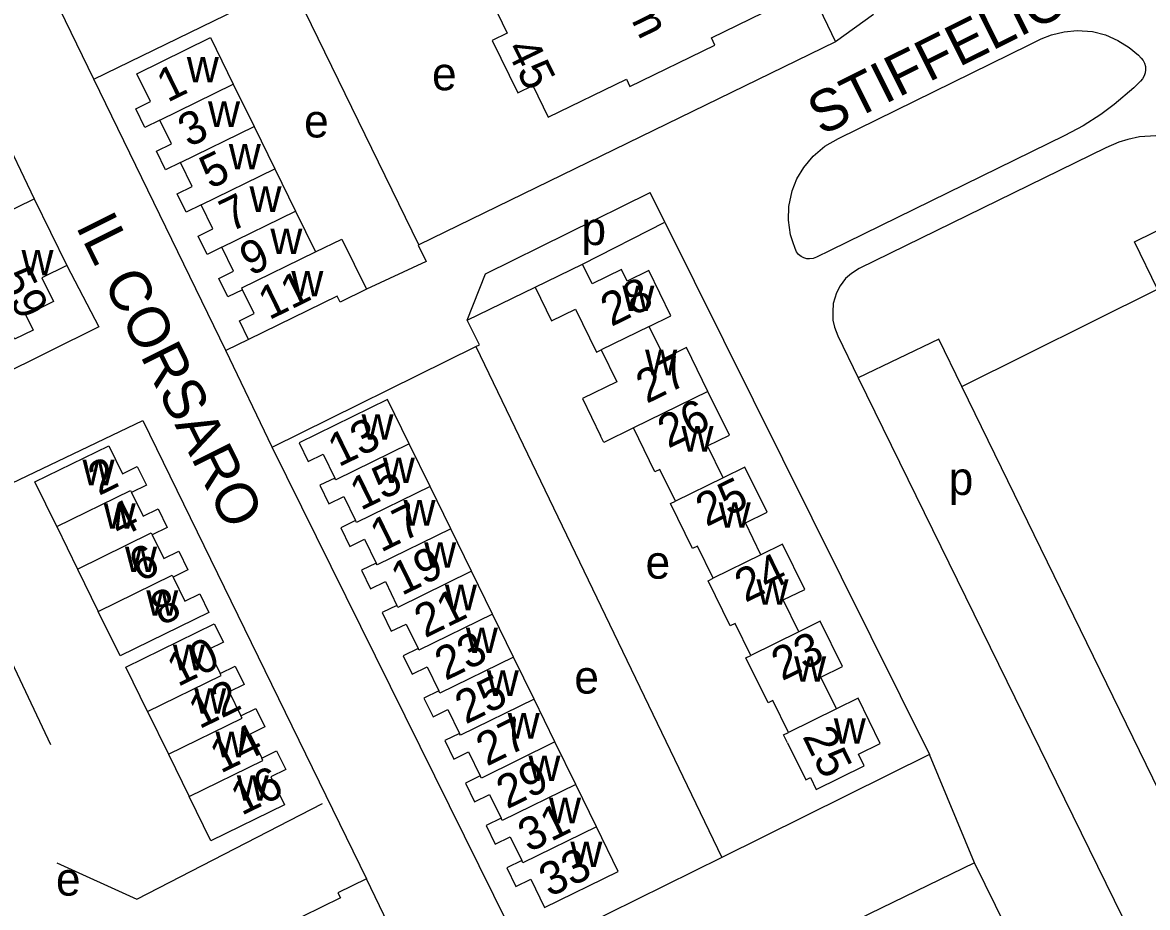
# Model space of a CAD drawing. Extents: x 159441 to 162086, y 388175 to 389787.
# Drawn here: x 161032.2 to 161168.1, y 389007.5 to 389114.4 of the extents above; entities that cross this region are included whole.
import ezdxf

# ---------------------------------------------------------------- set-up
doc = ezdxf.new("R2010")
doc.units = 0
for name, color, linetype in [('BLT_Basislijn', 7, 'Continuous'), ('BLT_Bebouwing', 7, 'Continuous'), ('BLT_Centroide', 7, 'Continuous'), ('BLT_Huisnummer', 7, 'Continuous'), ('BLT_Huisnummer_ tussenligend', 7, 'Continuous'), ('BLT_Huisnummer_reeks', 7, 'Continuous'), ('BLT_Onderverdeling_panden', 7, 'Continuous'), ('BLT_Straatnaam', 7, 'Continuous'), ('BLT_Vlakafsluiter', 7, 'Continuous')]:
    doc.layers.add(name, color=color, linetype=linetype)

msp = doc.modelspace()

# ---------------------------------------------------------------- linework, layer by layer
at = {"layer": 'BLT_Basislijn'}
for p, q in [((161040.84, 389107.5), (161034.48, 389120.57)), ((161040.84, 389107.5), (161064.68, 389119.13)), ((161080.09, 389087.51), (161064.68, 389119.13)), ((161134.99, 389115.31), (161130.39, 389112.02)), ((161056.77, 389074.76), (161040.84, 389107.5)), ((161088.14, 389084.03), (161108, 389093.82)), ((161109.79, 389090.25), (161108, 389093.82)), ((161080.95, 389085.51), (161073.75, 389082.15)), ((161085.9, 389078.44), (161088.14, 389084.03)), ((161145.68, 389070.41), (161169.3, 389082.16)), ((161059.51, 389076.1), (161056.77, 389074.76)), ((161062.38, 389063.07), (161056.77, 389074.76)), ((161086.97, 389075.23), (161116.67, 389013.57)), ((161022.8, 389054.2), (161035.58, 389027.21))]:
    msp.add_line(p, q, dxfattribs=at)
for points in [[(161115.18, 389143.74), (161130.39, 389112.02)], [(161130.39, 389112.02), (161080.09, 389087.51)], [(161029.44, 389101.75), (161033.6, 389093.07)], [(161176.24, 389092.68), (161172.92, 389099.4), (161172.69, 389099.74), (161172.4, 389100.01), (161171.67, 389100.34), (161171.1, 389100.47), (161169.11, 389100.68), (161167.1, 389100.54), (161165.72, 389100.25), (161164.64, 389099.91), (161163.06, 389099.23), (161133.27, 389084.67), (161132.32, 389084.05), (161131.62, 389083.46), (161130.97, 389082.58), (161130.54, 389081.72), (161130.13, 389080.43), (161130.07, 389079.41), (161130.08, 389078.44), (161130.29, 389077.57), (161130.67, 389076.54), (161133.15, 389071.47)], [(161169.3, 389082.16), (161166.52, 389087.87), (161176.24, 389092.68)], [(161099.83, 389085.19), (161109.79, 389090.25)], [(161109.79, 389090.25), (161141.77, 389025.97)], [(161080.09, 389087.51), (161080, 389087.46), (161080.95, 389085.51)], [(161037.55, 389085.01), (161041.45, 389077.62), (160998.37, 389056.26), (160996.9, 389059.31)], [(161085.9, 389078.44), (161094.12, 389082.4)], [(161086.97, 389075.23), (161087.39, 389075.43), (161085.9, 389078.44)], [(161145.68, 389070.41), (161142.9, 389076.12), (161133.15, 389071.47)], [(161062.38, 389063.07), (161086.97, 389075.23)], [(161133.15, 389071.47), (161220.85, 388892.53), (161222.4, 388889.35)], [(161222.4, 388889.35), (161222.83, 388889.21), (161223.51, 388889.06), (161224.2, 388888.98), (161224.89, 388888.98), (161225.58, 388889.07), (161226.26, 388889.23), (161226.91, 388889.46), (161227.53, 388889.78), (161228.12, 388890.16), (161228.65, 388890.6), (161229.13, 388891.1), (161229.55, 388891.66), (161229.9, 388892.26), (161230.18, 388892.89), (161230.39, 388893.56), (161230.52, 388894.24), (161230.57, 388894.93), (161230.54, 388895.63), (161230.43, 388896.32), (161230.24, 388896.99), (161229.98, 388897.63), (161145.68, 389070.41)], [(161014.05, 389050.68), (161046.74, 389066.3), (161073.76, 389010.99)], [(161092.7, 389001.72), (161062.38, 389063.07)], [(161141.77, 389025.97), (161116.67, 389013.57)], [(161036.37, 389012.9), (161046.01, 389008.52), (161068.43, 389020.09)], [(161116.67, 389013.57), (161092.7, 389001.72)], [(161147.21, 389012.91), (161121.83, 389000.58)], [(161144.66, 388953.98), (161170.1, 388966.39), (161147.21, 389012.91)]]:
    msp.add_lwpolyline(points, dxfattribs=at)
msp.add_lwpolyline([(161130.78, 389100.36), (161153.79, 389111.67), (161155.24, 389112.38), (161156.5, 389112.88), (161158.03, 389113.23), (161159.61, 389113.4), (161161.44, 389113.26), (161163, 389112.88), (161164.51, 389112.19), (161165.87, 389111.34), (161167, 389110.4), (161167.31, 389110.06), (161167.55, 389109.77), (161167.71, 389109.43), (161167.83, 389109.03), (161167.85, 389108.64), (161167.8, 389108.28), (161167.69, 389107.9), (161167.48, 389107.57), (161167.23, 389107.26), (161166.44, 389106.47), (161164.06, 389104.44), (161162.44, 389103.24), (161160.32, 389101.89), (161158.1, 389100.7), (161129.76, 389086.84), (161128.11, 389086.02), (161127.71, 389085.86), (161127.28, 389085.81), (161126.92, 389085.84), (161126.58, 389085.95), (161126.26, 389086.12), (161125.94, 389086.36), (161125.71, 389086.68), (161125.52, 389087.06), (161125.24, 389087.86), (161124.98, 389088.71), (161124.72, 389090.51), (161124.76, 389092.14), (161125.16, 389094.02), (161125.75, 389095.47), (161126.57, 389096.84), (161127.69, 389098.22), (161129.1, 389099.42)], close=True, dxfattribs=at)
at = {"layer": 'BLT_Bebouwing'}
for p, q in [((161057.67, 389106.93), (161060.18, 389101.81)), ((161060.18, 389101.81), (161062.69, 389096.69)), ((161062.69, 389096.69), (161065.2, 389091.57)), ((161065.2, 389091.57), (161067.61, 389086.67)), ((161094.12, 389082.4), (161099.83, 389085.19)), ((161073.75, 389082.15), (161070.58, 389080.6)), ((161081.43, 389058.35), (161078.92, 389063.49)), ((161083.94, 389053.23), (161081.43, 389058.35)), ((161036.34, 389053.51), (161038.86, 389048.38)), ((161086.45, 389048.1), (161083.94, 389053.23)), ((161038.86, 389048.38), (161041.36, 389043.26)), ((161088.98, 389042.93), (161086.45, 389048.1)), ((161091.51, 389037.75), (161088.98, 389042.93)), ((161094, 389032.66), (161091.51, 389037.75)), ((161096.52, 389027.5), (161094, 389032.66)), ((161047.3, 389031.18), (161049.83, 389026.03)), ((161099.03, 389022.38), (161096.52, 389027.5)), ((161049.83, 389026.03), (161052.33, 389020.92)), ((161101.53, 389017.26), (161099.03, 389022.38)), ((161077.03, 389004.24), (161073.76, 389010.99))]:
    msp.add_line(p, q, dxfattribs=at)
for points in [[(161118.04, 389131.1), (161108.61, 389126.51), (161107.47, 389128.84), (161097.17, 389123.83), (161098.32, 389121.48), (161088.89, 389116.88), (161090.75, 389113.06), (161088.94, 389112.18), (161092.02, 389105.86), (161093.84, 389106.74), (161095.7, 389102.92), (161105.15, 389107.53)], [(161105.15, 389107.53), (161105.58, 389106.64), (161115.84, 389111.64), (161115.41, 389112.52), (161124.85, 389117.12), (161123.83, 389119.24), (161122.99, 389120.96), (161124.8, 389121.84), (161121.71, 389128.17), (161119.9, 389127.29), (161118.04, 389131.1)], [(161045.88, 389103.94), (161047.67, 389104.82), (161046.02, 389108.18), (161054.92, 389112.55), (161057.67, 389106.93)], [(161048.78, 389102.58), (161046.98, 389101.7), (161045.88, 389103.94)], [(161051.28, 389097.46), (161049.49, 389096.58), (161048.39, 389098.81), (161050.19, 389099.69), (161048.78, 389102.58)], [(161053.79, 389092.34), (161051.99, 389091.46), (161050.9, 389093.69), (161052.7, 389094.57), (161051.28, 389097.46)], [(161030.71, 389088.78), (161029.58, 389091.1), (161033.6, 389093.07)], [(161033.6, 389093.07), (161037.55, 389085.01)], [(161056.3, 389087.22), (161054.5, 389086.34), (161053.41, 389088.57), (161055.2, 389089.45), (161053.79, 389092.34)], [(161067.61, 389086.67), (161070.77, 389088.22), (161073.75, 389082.15)], [(161058.8, 389082.1), (161057.01, 389081.22), (161055.91, 389083.45), (161057.71, 389084.33), (161056.3, 389087.22)], [(161037.55, 389085.01), (161034.56, 389083.55)], [(161107.91, 389077.67), (161110.52, 389078.95), (161107.85, 389084.41), (161105.24, 389083.13), (161104.55, 389084.54), (161101, 389082.8), (161099.83, 389085.19)], [(161034.56, 389083.55), (161035.97, 389080.67), (161032.61, 389079.02)], [(161059.51, 389076.1), (161058.41, 389078.35), (161060.21, 389079.23), (161058.8, 389082.1)], [(161070.58, 389080.6), (161070.23, 389081.31), (161059.51, 389076.1)], [(161094.12, 389082.4), (161096.11, 389078.34), (161098.99, 389079.75), (161101.54, 389074.55), (161102.12, 389074.84)], [(161032.61, 389079.02), (161033.49, 389077.22), (161031.25, 389076.12), (161030.37, 389077.92)], [(161115, 389069.8), (161112.4, 389075.11), (161109.79, 389073.83), (161107.91, 389077.67)], [(161102.12, 389074.84), (161104, 389070.99), (161099.83, 389068.95), (161102.03, 389064.45)], [(161116.85, 389059.4), (161114.96, 389063.25), (161117.58, 389064.53), (161115, 389069.8)], [(161078.92, 389063.49), (161076.3, 389068.85), (161065.62, 389063.61), (161066.72, 389061.36), (161068.52, 389062.24), (161069.92, 389059.36)], [(161106.01, 389065.41), (161102.42, 389063.65), (161102.03, 389064.45)], [(161111.06, 389056.56), (161109.18, 389060.41), (161108.59, 389060.13), (161106.01, 389065.41)], [(161036.34, 389053.51), (161033.71, 389058.89), (161042.62, 389063.26), (161044.27, 389059.88), (161046.07, 389060.76), (161047.17, 389058.51), (161045.37, 389057.63)], [(161121.4, 389050.1), (161119.52, 389053.95), (161122.13, 389055.23), (161119.46, 389060.68), (161116.85, 389059.4)], [(161069.92, 389059.36), (161068.12, 389058.49), (161069.22, 389056.24), (161071.02, 389057.12), (161072.43, 389054.23)], [(161045.37, 389057.63), (161046.78, 389054.75), (161048.58, 389055.64), (161049.68, 389053.4), (161047.88, 389052.51)], [(161115.61, 389047.26), (161113.72, 389051.12), (161113.14, 389050.84), (161110.48, 389056.28), (161111.06, 389056.56)], [(161072.43, 389054.23), (161070.64, 389053.35), (161071.73, 389051.11), (161073.53, 389051.99), (161074.94, 389049.1)], [(161047.88, 389052.51), (161049.29, 389049.64), (161051.09, 389050.52), (161052.19, 389048.27), (161050.39, 389047.39)], [(161125.96, 389040.79), (161124.07, 389044.64), (161126.68, 389045.92), (161124.01, 389051.38), (161121.4, 389050.1)], [(161074.94, 389049.1), (161073.14, 389048.23), (161074.24, 389045.98), (161076.04, 389046.86), (161077.44, 389043.99)], [(161050.39, 389047.39), (161051.81, 389044.5), (161053.61, 389045.38), (161054.71, 389043.13), (161044, 389037.88), (161041.36, 389043.26)], [(161120.17, 389037.95), (161118.28, 389041.8), (161117.7, 389041.52), (161115.03, 389046.97), (161115.61, 389047.26)], [(161077.44, 389043.99), (161075.65, 389043.11), (161076.74, 389040.87), (161078.54, 389041.74), (161079.98, 389038.79)], [(161130.51, 389031.49), (161128.62, 389035.33), (161131.24, 389036.61), (161128.57, 389042.07), (161125.96, 389040.79)], [(161047.3, 389031.18), (161044.68, 389036.53), (161055.37, 389041.78), (161056.47, 389039.53), (161054.68, 389038.65), (161056.09, 389035.78)], [(161079.98, 389038.79), (161078.19, 389037.91), (161079.28, 389035.67), (161081.08, 389036.55), (161082.48, 389033.67)], [(161124.71, 389028.66), (161122.84, 389032.49), (161122.26, 389032.21), (161119.59, 389037.67), (161120.17, 389037.95)], [(161056.09, 389035.78), (161057.88, 389036.66), (161058.98, 389034.42), (161057.18, 389033.54), (161058.6, 389030.66)], [(161082.48, 389033.67), (161080.69, 389032.8), (161081.79, 389030.55), (161083.58, 389031.43), (161084.99, 389028.54)], [(161124.61, 389027.4), (161126.81, 389022.91), (161127.39, 389023.19), (161128.08, 389021.78), (161133.88, 389024.62), (161133.19, 389026.03), (161135.79, 389027.3), (161133.12, 389032.77), (161130.51, 389031.49)], [(161058.6, 389030.66), (161060.39, 389031.54), (161061.49, 389029.31), (161059.69, 389028.43), (161061.11, 389025.55)], [(161084.99, 389028.54), (161083.2, 389027.66), (161084.3, 389025.42), (161086.09, 389026.3), (161087.5, 389023.42)], [(161124.61, 389027.4), (161124.13, 389028.37), (161124.71, 389028.66)], [(161061.11, 389025.55), (161062.9, 389026.43), (161064, 389024.18), (161062.21, 389023.3), (161063.86, 389019.92), (161054.96, 389015.56), (161052.33, 389020.92)], [(161087.5, 389023.42), (161085.71, 389022.54), (161086.8, 389020.29), (161088.6, 389021.17), (161090.01, 389018.29)], [(161090.01, 389018.29), (161088.21, 389017.41), (161089.31, 389015.17), (161091.1, 389016.05), (161092.51, 389013.17)], [(161092.51, 389013.17), (161090.71, 389012.3), (161091.81, 389010.05), (161093.62, 389010.93), (161095.26, 389007.53), (161104.16, 389011.88), (161101.53, 389017.26)], [(161073.76, 389010.99), (161070.29, 389009.3), (161070.6, 389008.67), (161066.02, 389006.43)]]:
    msp.add_lwpolyline(points, dxfattribs=at)
at = {"layer": 'BLT_Onderverdeling_panden'}
for p, q in [((161048.78, 389102.58), (161057.67, 389106.93)), ((161051.28, 389097.46), (161060.18, 389101.81)), ((161053.79, 389092.34), (161062.69, 389096.69)), ((161056.3, 389087.22), (161065.2, 389091.57)), ((161107.91, 389077.67), (161102.12, 389074.84)), ((161115, 389069.8), (161106.01, 389065.41)), ((161116.85, 389059.4), (161111.06, 389056.56)), ((161036.34, 389053.51), (161045.26, 389057.86)), ((161045.26, 389057.86), (161045.37, 389057.63)), ((161038.86, 389048.38), (161047.77, 389052.73)), ((161047.77, 389052.73), (161047.88, 389052.51)), ((161121.4, 389050.1), (161115.61, 389047.26)), ((161041.36, 389043.26), (161050.28, 389047.62)), ((161050.28, 389047.62), (161050.39, 389047.39)), ((161125.96, 389040.79), (161120.17, 389037.95)), ((161047.3, 389031.18), (161056.21, 389035.53)), ((161056.21, 389035.53), (161056.09, 389035.78)), ((161130.51, 389031.49), (161124.71, 389028.66)), ((161049.83, 389026.03), (161058.73, 389030.38)), ((161058.73, 389030.38), (161058.6, 389030.66)), ((161052.33, 389020.92), (161061.24, 389025.27)), ((161061.24, 389025.27), (161061.11, 389025.55))]:
    msp.add_line(p, q, dxfattribs=at)
for points in [[(161058.8, 389082.1), (161058.7, 389082.32), (161067.61, 389086.67)], [(161078.92, 389063.49), (161070.04, 389059.13), (161069.92, 389059.36)], [(161081.43, 389058.35), (161072.55, 389053.99), (161072.43, 389054.23)], [(161083.94, 389053.23), (161075.05, 389048.87), (161074.94, 389049.1)], [(161086.45, 389048.1), (161077.56, 389043.75), (161077.44, 389043.99)], [(161088.98, 389042.93), (161080.09, 389038.57), (161079.98, 389038.79)], [(161091.51, 389037.75), (161082.62, 389033.39), (161082.48, 389033.67)], [(161094, 389032.66), (161085.11, 389028.3), (161084.99, 389028.54)], [(161096.52, 389027.5), (161087.63, 389023.14), (161087.5, 389023.42)], [(161099.03, 389022.38), (161090.14, 389018.02), (161090.01, 389018.29)], [(161101.53, 389017.26), (161092.64, 389012.9), (161092.51, 389013.17)]]:
    msp.add_lwpolyline(points, dxfattribs=at)
at = {"layer": 'BLT_Vlakafsluiter'}
msp.add_line((161147.21, 389012.91), (161141.77, 389025.97), dxfattribs=at)

# ---------------------------------------------------------------- texts
at = {"layer": 'BLT_Centroide'}
for s, p in [('w', (161052.06, 389107.12)), ('e', (161081.67, 389106.18)), ('w', (161054.62, 389101.75)), ('e', (161066.22, 389100.48)), ('w', (161057.13, 389096.62)), ('w', (161059.63, 389091.5)), ('w', (161062.15, 389086.41)), ('p', (161099.72, 389087.49)), ('w', (161032.09, 389083.83)), ('w', (161064.68, 389081.28)), ('w', (161104.66, 389079.53)), ('w', (161107.41, 389071.77)), ('w', (161073.16, 389064)), ('w', (161111.8, 389062.56)), ('w', (161039.46, 389058.5)), ('w', (161075.73, 389058.75)), ('p', (161144.07, 389057.32)), ('w', (161042.02, 389053.25)), ('w', (161078.23, 389053.62)), ('w', (161116.3, 389053.36)), ('w', (161080.73, 389048.53)), ('w', (161044.59, 389048)), ('e', (161107.46, 389047.21)), ('w', (161083.23, 389043.41)), ('w', (161120.86, 389044.06)), ('w', (161047.16, 389042.75)), ('w', (161085.76, 389038.22)), ('w', (161050.38, 389036.16)), ('w', (161125.41, 389034.77)), ('e', (161098.86, 389033.34)), ('w', (161088.29, 389033.06)), ('w', (161052.95, 389030.91)), ('w', (161090.81, 389027.91)), ('w', (161130.2, 389027.28)), ('w', (161055.52, 389025.66)), ('w', (161093.32, 389022.78)), ('w', (161058.09, 389020.41)), ('w', (161095.8, 389017.69)), ('w', (161098.38, 389012.41)), ('e', (161036.25, 389008.95))]:
    msp.add_text(s, height=4, dxfattribs=at).set_placement(p)
at = {"layer": 'BLT_Huisnummer'}
for s, rotation, p in [('1', 26.0655, (161049.72, 389104.66)), ('5', 26.0655, (161054.88, 389094.19)), ('59', 296.0549, (161029.32, 389083.59)), ('11', 26.0655, (161061.99, 389078.39)), ('28', 26.0641, (161103.32, 389077.59)), ('26', 26.0641, (161110.21, 389062.89)), ('13', 26.0655, (161070.39, 389060.64)), ('2', 26.063, (161041.43, 389057.18)), ('17', 26.0655, (161075.5, 389050.34)), ('24', 26.0641, (161119.51, 389044.28)), ('8', 26.063, (161048.98, 389041.47)), ('21', 26.0655, (161080.82, 389040)), ('10', 26.063, (161050.96, 389034.11)), ('25', 26.0655, (161085.74, 389029.59)), ('25', 296.0661, (161126.36, 389028.18)), ('16', 26.063, (161058.66, 389018.56)), ('29', 26.0655, (161090.74, 389019.35)), ('33', 26.0655, (161095.88, 389008.72))]:
    msp.add_text(s, height=4, rotation=rotation, dxfattribs=at).set_placement(p)
at = {"layer": 'BLT_Huisnummer_ tussenligend'}
for s, rotation, p in [('3', 26.0655, (161052.28, 389099.23)), ('7', 26.0655, (161057.31, 389089)), ('9', 26.0655, (161059.74, 389083.7)), ('27', 26.0641, (161107.6, 389068.3)), ('15', 26.0655, (161073.06, 389055.39)), ('25', 26.0641, (161114.81, 389053.43)), ('4', 26.063, (161043.93, 389052.07)), ('6', 26.063, (161046.38, 389046.73)), ('19', 26.0655, (161078.01, 389045.11)), ('23', 26.0655, (161083.3, 389034.85)), ('23', 26.0641, (161123.95, 389034.82)), ('12', 26.063, (161053.57, 389029.01)), ('27', 26.0655, (161088.29, 389024.52)), ('14', 26.063, (161056.14, 389023.66)), ('31', 26.0655, (161093.35, 389014.12))]:
    msp.add_text(s, height=4, rotation=rotation, dxfattribs=at).set_placement(p)
at = {"layer": 'BLT_Huisnummer_reeks'}
for s, rotation, p in [('t/m', 295.9867, (161103.69, 389118.79)), ('45', 296.0548, (161090.54, 389111.22))]:
    msp.add_text(s, height=4, rotation=rotation, dxfattribs=at).set_placement(p)
at = {"layer": 'BLT_Straatnaam'}
for s, rotation, p in [('STIFFELIO', 26.5309, (161128.7, 389100.64)), ('IL CORSARO', 296.5309, (161038.58, 389089.76))]:
    msp.add_text(s, height=5, rotation=rotation, dxfattribs=at).set_placement(p)

doc.saveas('drawing.dxf')
